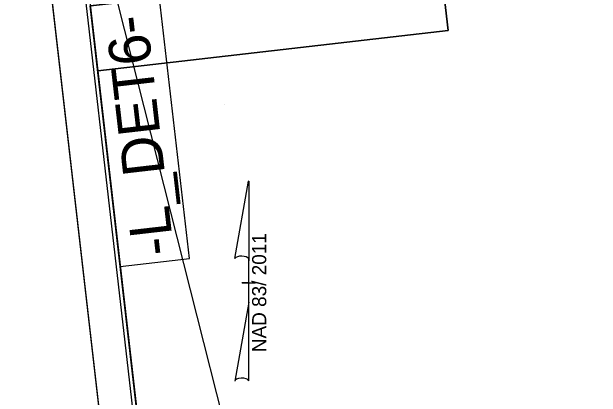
# Model space of a CAD drawing. Extents: x 474105 to 475385, y 502977 to 504774.
# Drawn here: x 474105.4 to 474458.9, y 504201.4 to 504432.7 of the extents above; entities that cross this region are included whole.
import ezdxf

# ---------------------------------------------------------------- set-up
doc = ezdxf.new("R2010")
doc.units = 0
for name, color, linetype in [('Old_Level_1', 7, 'Continuous'), ('Prop Grid Mask', 7, 'Continuous'), ('Prop North Arrow NAD83 for Plan Sheets CELL', 7, 'Continuous'), ('Sheet Cutting Line CELL', 7, 'Continuous'), ('Sheet Layout Plan Border', 7, 'Continuous'), ('Sheet North Arrow Point CELL', 7, 'Continuous'), ('Sheet Plan CELL', 7, 'Continuous'), ('Sheet Plan Layout CELL', 7, 'Continuous'), ('Sheet Plot Border Inside CELL', 7, 'Continuous'), ('Sheet Plot Border Outside CELL', 7, 'Continuous')]:
    doc.layers.add(name, color=color, linetype=linetype)

msp = doc.modelspace()

# ---------------------------------------------------------------- linework, layer by layer
at = {"layer": 'Prop Grid Mask'}
msp.add_lwpolyline([(474152.5, 504436.15), (474170.46, 504279.81), (474211.89, 504284.57), (474193.93, 504440.91)], close=True, dxfattribs=at)
at = {"layer": 'Prop North Arrow NAD83 for Plan Sheets CELL'}
for p, q in [((474239.25, 504284.59), (474247.45, 504330.94)), ((474247.5, 504330.94), (474247.45, 504330.94)), ((474247.5, 504330.94), (474247.45, 504330.94)), ((474247.5, 504330.94), (474247.5, 504283.14)), ((474247.5, 504258.34), (474247.5, 504284.54)), ((474247.5, 504283.14), (474247.5, 504284.49)), ((474243.5, 504269.94), (474243.45, 504269.94)), ((474247.05, 504269.94), (474243.5, 504269.94)), ((474243.55, 504269.94), (474251.55, 504269.94)), ((474247.5, 504258.34), (474239.15, 504211.09)), ((474247.55, 504211.29), (474247.5, 504258.34))]:
    msp.add_line(p, q, dxfattribs=at)
for centre, start_param, end_param in [((474243.38, 504284.09), 0.216388, 2.908219), ((474243.38, 504210.92), 0.201328, 3.141593)]:
    msp.add_ellipse(centre, major_axis=(4.23, -0.03), ratio=0.461098, start_param=start_param, end_param=end_param, dxfattribs=at)
at = {"layer": 'Sheet Cutting Line CELL'}
msp.add_line((474105.4, 504649.22), (474297.55, 502976.72), dxfattribs=at)
at = {"layer": 'Sheet Layout Plan Border'}
msp.add_lwpolyline([(475344.02, 503264.53), (475192.28, 504585.29), (475112.79, 504576.16), (474903.65, 504485.25), (474306.12, 504619.67), (474302.09, 504654.7), (474324.93, 504455.97), (474152.51, 504436.16), (474168.76, 504438.03), (474279.78, 503999.56), (474242.05, 503987.59), (474254.81, 503913.6), (474216.7, 503877.46), (474300.89, 503144.66)], close=True, dxfattribs=at)
at = {"layer": 'Sheet North Arrow Point CELL'}
msp.add_line((474232.74, 504376.85), (474232.74, 504376.85), dxfattribs=at)
at = {"layer": 'Sheet Plan CELL'}
for points in [[(474129.67, 504634.92), (474300.88, 503144.68), (475344.02, 503264.53), (475172.82, 504754.74)], [(475344.02, 503264.53), (474300.91, 503144.66), (474152.5, 504436.15), (474301.58, 504453.29), (474278.76, 504652.02), (475172.82, 504754.74)]]:
    msp.add_lwpolyline(points, close=True, dxfattribs=at)
at = {"layer": 'Sheet Plan Layout CELL'}
for points in [[(474300.91, 503144.66), (475344.02, 503264.53), (475172.82, 504754.73), (474339.78, 504659.02), (474367.09, 504421.33), (474156.99, 504397.2)], [(474367.09, 504421.33), (474339.78, 504659.05), (474129.67, 504634.93), (474156.99, 504397.2)]]:
    msp.add_lwpolyline(points, close=True, dxfattribs=at)
at = {"layer": 'Sheet Plot Border Inside CELL'}
msp.add_lwpolyline([(475364.04, 503112.33), (475173.87, 504767.43), (474125.78, 504647.03), (474315.93, 502991.92)], close=True, dxfattribs=at)
at = {"layer": 'Sheet Plot Border Outside CELL'}
msp.add_lwpolyline([(475385.39, 503101.7), (475193.24, 504774.2), (474105.4, 504649.22), (474297.55, 502976.72)], close=True, dxfattribs=at)

# ---------------------------------------------------------------- texts
at = {"layer": 'Old_Level_1'}
msp.add_text('-L_DET6-', height=25, rotation=96.5538, dxfattribs=at).set_placement((474202.81, 504287.62))
at = {"layer": 'Prop North Arrow NAD83 for Plan Sheets CELL'}
msp.add_text('NAD 83/ 2011', height=8.5, rotation=90, dxfattribs=at).set_placement((474258.02, 504228.42))

doc.saveas('drawing.dxf')
